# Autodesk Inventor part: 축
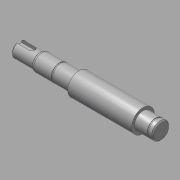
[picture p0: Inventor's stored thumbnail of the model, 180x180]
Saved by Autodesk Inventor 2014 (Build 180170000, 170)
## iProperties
Created: 2015-12
Part Number: 축
Material: 강철, 연강
Document SubType Name: Modeling
Designer: mduedu
Density: 7.86 g/cm^3
Appearance: 강철
Author: mduedu
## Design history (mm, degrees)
sketch "스케치1"
  geometry: L1 (-62.5, 0)-(62.5, 0); L2 (-62.5, 0)-(-62.5, 6.5); L3 (-62.5, 6.5)-(-43.5, 6.5); L4 (-43.5, 7)-(-42.634, 7.5); L5 (-42.634, 7.5)-(-9.5, 7.5); L6 (-9.5, 7.5)-(-9.5, 10); L7 (-9.5, 10)-(46.5, 10); L8 (46.5, 10)-(46.5, 7.5); L9 (46.5, 7.5)-(62.5, 7.5); L10 (62.5, 7.5)-(62.5, 0); L11 (-43.5, 6.5)-(-43.5, 7); 2 further points
  constraints: 22 end point, 6 parallel, 2 perpendicular, 1 coincident, 1 horizontal, 1 midpoint, 1 vertical
  dimensions: "d0" = 13 diameter of L3 L1; "d2" = 15 diameter of L5 L1; "d3" = 20 diameter of L7 L1; "d5" = 15 diameter of L9 L1; "d6" = 125 distance of L1.start L1.end; "d7" = 19 distance of L2.end L3.end; "d8" = 34 distance from line of L6 L3.end; "d9" = 56 distance of L6.end L7.end; "d41" = 14 diameter of L4.start L1; "d42" = 30 deg angle of L4 L3
revolve "회전1" sketch "스케치1" stored, may be unused: angle "d11" = 90 deg
node "작업 평면1"
node "작업 평면2"
sketch "스케치3"
  geometry: L1 (9.5, -2.5)-(-2.5, -2.5); L2 (-2.5, 2.5)-(9.5, 2.5); L3 (9.5, 2.5)-(9.5, -2.5); L4 (9.5, 6.5)-(9.5, -6.5) reference; A1 r 2.5 centre (-2.5, 0) between (-2.5, 2.5) and (-2.5, -2.5); 1 further point
  constraints: 6 end point, 2 point on circle, 2 tangent, 1 centre point, 1 collinear, 1 horizontal, 1 horizontal alignment, 1 parallel
  dimensions: "d17" = 5 distance of L2.end L1.start; "d19" = 12 distance from line of A1.centre L3
extrude "돌출2" cut sketch "스케치3" distance "d20" = 3; taper "d21" = 0 deg
chamfer "모따기1" distance "d22" = 1; stored, may be unused: second distance "d23" = 2, angle "d24" = 45 deg
fillet "모깎기1" dims "d25" = 3
sketch "스케치4"
  geometry: L1 (-9.5, -10)-(-9.5, 10) reference; L2 (-9.5, 0)-(0, 0); L3 (-26.65, 12.15)-(-25.5, 12.15); L4 (-25.5, 12.15)-(-25.5, 7.15); L5 (-25.5, 7.15)-(-26.65, 7.15); L6 (-26.65, 7.15)-(-26.65, 12.15); L7 (57.5, 12.15)-(58.65, 12.15); L8 (58.65, 12.15)-(58.65, 7.15); L9 (58.65, 7.15)-(57.5, 7.15); L10 (57.5, 7.15)-(57.5, 12.15); L11 (62.5, -7.5)-(62.5, 7.5) reference
  constraints: 18 end point, 4 parallel, 2 horizontal, 2 perpendicular, 1 midpoint
  dimensions: "d26" = 16 distance between parallel lines of L4 L1; "d27" = 1.15 distance of L3.start L3.end; "d28" = 14.3 diameter of L5 L2; "d29" = 5 distance of L3.end L4.end; "d30" = 1.15 distance of L7.start L7.end; "d31" = 5 distance of L7.end L8.end; "d32" = 5 distance between parallel lines of L10 L11; "d33" = 14.3 diameter of L9 L2
revolve "회전2" sketch "스케치4" stored, may be unused: angle "d34" = 90 deg
chamfer "모따기2" distance "d35" = 1; stored, may be unused: second distance "d36" = 2, angle "d37" = 45 deg
sketch "스케치5"
  geometry: 2 further points
  constraints: 1 coincident
sketch "스케치6"
  geometry: 1 further point
hole "구멍1" sketch "스케치6" at (2.5, -3.5) diameter "d43" = 4.917; stored, may be unused: countersink angle "d47" = 90 deg, drill point angle "d49" = 120 deg; dims "d44" = 14, "d45" = 4, "d46" = 2, "d48" = 17
node "솔리드1"
other parameters: "d12" = -15.5
